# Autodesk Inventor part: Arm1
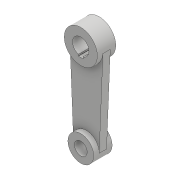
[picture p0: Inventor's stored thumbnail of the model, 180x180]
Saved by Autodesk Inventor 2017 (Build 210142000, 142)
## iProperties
Created: 2016-05
Part Number: Arm1
Material: Generic
Document SubType Name: Modeling
Designer: CADCIM
Density: 1 g/cm^3
Appearance: Default
Author: CADCIM
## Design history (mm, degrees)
sketch "Sketch1"
  geometry: C1 r 56.25 at (0, 0); C2 r 28 at (0, 0); C3 r 43.75 at (0, -300); C4 r 21.75 at (0, -300); 1 further point
  constraints: 4 centre point, 3 coincident
  dimensions: "d0" = 112.5 diameter of C1; "d1" = 56 diameter of C2; "d2" = 87.5 diameter of C3; "d3" = 43.5 diameter of C4; "d4" = 300 distance of C4.centre C2.centre
extrude "Extrusion1" new body sketch "Sketch1" stored distance "d5" = 62.5; taper "d6" = 0 deg
sketch "Sketch2"
  geometry: L1 (56.201, -2.344)-(43.712, -301.823); L2 (-56.201, -2.344)-(-43.712, -301.823); A1 r 56.25 centre (0, 0) between (-56.201, -2.344) and (56.201, -2.344); A2 r 43.75 centre (0, -300) between (43.712, -301.823) and (-43.712, -301.823); 3 further points
  constraints: 4 end point, 4 point on circle, 2 centre point, 2 coincident
extrude "Extrusion2" join sketch "Sketch2" stored distance "d7" = 25; taper "d8" = 0 deg
sketch "Sketch3"
  geometry: L1 (0, 0)-(0, 99.622); L2 (-8, 26.833)-(8, 26.833); L3 (8, 26.833)-(8, 32.3); L4 (8, 32.3)-(-8, 32.3); L5 (-8, 32.3)-(-8, 26.833); L6 (0, 0)-(0, -28); A1 r 28 centre (0, 0) between (-8, 26.833) and (8, 26.833) reference
  constraints: 12 end point, 3 point on circle, 2 parallel, 2 vertical, 1 horizontal, 1 perpendicular, 1 other
  dimensions: "d10" = 16 distance of L3.end L4.end; "d11" = 60.3 distance from line of L4 L6.end
extrude "Extrusion3" cut sketch "Sketch3" stored distance "d12" = 25; taper "d13" = 0 deg
fillet "Fillet1" dims "d14" = 0.4
body "Solid1"
